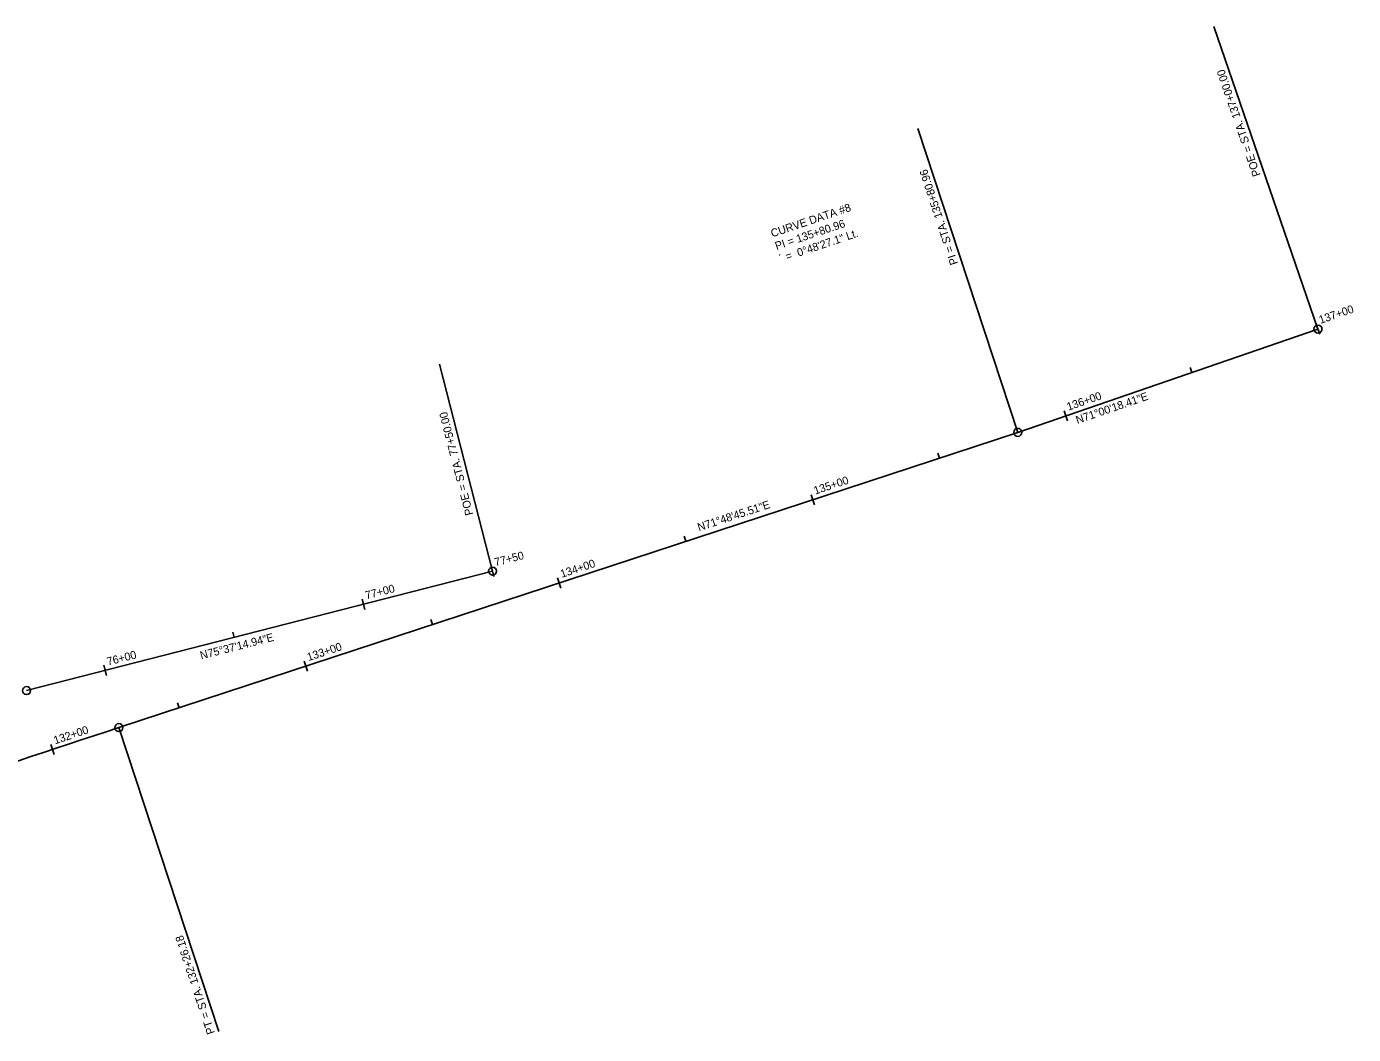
# Model space of a CAD drawing. Extents: x 1667099 to 1669772, y 337408 to 340124.
# Drawn here: x 1669274 to 1669771.5, y 339746.1 to 340124.1 of the extents above; entities that cross this region are included whole.
import ezdxf

# ---------------------------------------------------------------- set-up
doc = ezdxf.new("R2010")
doc.units = 0
for name, color, linetype in [('Alignment', 7, 'Continuous'), ('D_Roadway_Centerline', 7, 'Continuous'), ('D_Roadway_Centerline_Bearings', 7, 'Continuous'), ('D_Roadway_Centerline_CurveData', 7, 'Continuous'), ('D_Roadway_Centerline_Flags', 7, 'Continuous'), ('D_Roadway_Centerline_Text', 7, 'Continuous'), ('S_Roadway_Edge_Pavement', 7, 'Continuous')]:
    doc.layers.add(name, color=color, linetype=linetype)

msp = doc.modelspace()

# ---------------------------------------------------------------- linework, layer by layer
at = {"layer": 'Alignment'}
msp.add_line((1669273.99, 339875.07), (1669448.75, 339919.87), dxfattribs=at)
at = {"layer": 'D_Roadway_Centerline'}
for p, q in [((1669645.68, 339971.94), (1669758.23, 340010.68)), ((1669308.61, 339861.2), (1669645.68, 339971.94)), ((1669273.99, 339875.07), (1669448.75, 339919.87))]:
    msp.add_line(p, q, dxfattribs=at)
msp.add_arc((1676524.41, 317897.9), 23118.26, 108.187357, 108.973714, dxfattribs=at)
at = {"layer": 'D_Roadway_Centerline_Flags'}
for points in [[(1669758.23, 340010.68), (1669719.17, 340124.15)], [(1669645.68, 339971.94), (1669608.22, 340085.94)], [(1669448.75, 339919.87), (1669428.85, 339997.49)], [(1669308.61, 339861.2), (1669346.07, 339747.19)]]:
    msp.add_lwpolyline(points, dxfattribs=at)
for centre in [(1669758.23, 340010.68), (1669645.68, 339971.94), (1669448.75, 339919.87), (1669273.99, 339875.07), (1669308.61, 339861.2)]:
    msp.add_circle(centre, 1.5, dxfattribs=at)
at = {"layer": 'D_Roadway_Centerline_Text'}
for points in [[(1669757.58, 340012.57), (1669758.88, 340008.79)], [(1669710.3, 339996.3), (1669710.95, 339994.41)], [(1669663.02, 339980.02), (1669664.33, 339976.24)], [(1669615.63, 339964.17), (1669616.26, 339962.27)], [(1669568.13, 339948.56), (1669569.38, 339944.76)], [(1669520.63, 339932.96), (1669521.25, 339931.06)], [(1669448.25, 339921.81), (1669449.25, 339917.93)], [(1669448.25, 339921.81), (1669449.25, 339917.93)], [(1669473.13, 339917.35), (1669474.38, 339913.55)], [(1669399.82, 339909.39), (1669400.81, 339905.51)], [(1669425.63, 339901.75), (1669426.25, 339899.85)], [(1669351.39, 339896.97), (1669351.88, 339895.03)], [(1669302.95, 339884.56), (1669303.95, 339880.68)], [(1669378.12, 339886.14), (1669379.37, 339882.34)], [(1669330.62, 339870.53), (1669331.25, 339868.63)], [(1669283.12, 339854.91), (1669284.38, 339851.11)]]:
    msp.add_lwpolyline(points, dxfattribs=at)
at = {"layer": 'S_Roadway_Edge_Pavement'}
for p, q in [((1669645.68, 339971.94), (1669758.23, 340010.68)), ((1669308.61, 339861.2), (1669645.68, 339971.94))]:
    msp.add_line(p, q, dxfattribs=at)
msp.add_arc((1676524.41, 317897.9), 23118.26, 108.187357, 108.973714, dxfattribs=at)

# ---------------------------------------------------------------- texts
at = {"layer": 'D_Roadway_Centerline_Bearings'}
for s, rotation, p in [('N71%%d00\'18.41"E', 18.9949, (1669668.03, 339975.05)), ('N71%%d48\'45.51"E', 18.1874, (1669526.13, 339934.8)), ('N75%%d37\'14.94"E', 14.3792, (1669339.48, 339886.75))]:
    msp.add_text(s, height=3, rotation=rotation, dxfattribs=at).set_placement(p)
at = {"layer": 'D_Roadway_Centerline_CurveData'}
for s, p in [('CURVE DATA #8', (1669553.63, 340045.04)), ('PI = 135+80.96', (1669555.23, 340040.3)), ('´ =  0%%d48\'27.1" Lt.', (1669556.82, 340035.56))]:
    msp.add_text(s, height=3, rotation=18.5911, dxfattribs=at).set_placement(p)
at = {"layer": 'D_Roadway_Centerline_Flags'}
for s, rotation, p in [('POE = STA. 137+00.00', 108.9949, (1669736.75, 340068.48)), ('PI = STA. 135+80.96', 108.1874, (1669623.29, 340035.28)), ('POE = STA. 77+50.00', 104.3792, (1669441.53, 339941.19)), ('PT = STA. 132+26.18', 108.1874, (1669344.64, 339746.72))]:
    msp.add_text(s, height=3, rotation=rotation, dxfattribs=at).set_placement(p)
at = {"layer": 'D_Roadway_Centerline_Text'}
for s, rotation, p in [('137+00', 18.9949, (1669759.16, 340012.59)), ('136+00', 18.9949, (1669664.61, 339980.04)), ('135+00', 18.1874, (1669569.71, 339948.56)), ('77+50', 14.3792, (1669449.83, 339921.69)), ('77+50', 14.3792, (1669449.83, 339921.69)), ('134+00', 18.1874, (1669474.71, 339917.35)), ('77+00', 14.3792, (1669401.4, 339909.28)), ('133+00', 18.1874, (1669379.71, 339886.13)), ('76+00', 14.3792, (1669304.53, 339884.44)), ('132+00', 18.2522, (1669284.7, 339854.91))]:
    msp.add_text(s, height=3, rotation=rotation, dxfattribs=at).set_placement(p)

doc.saveas('drawing.dxf')
